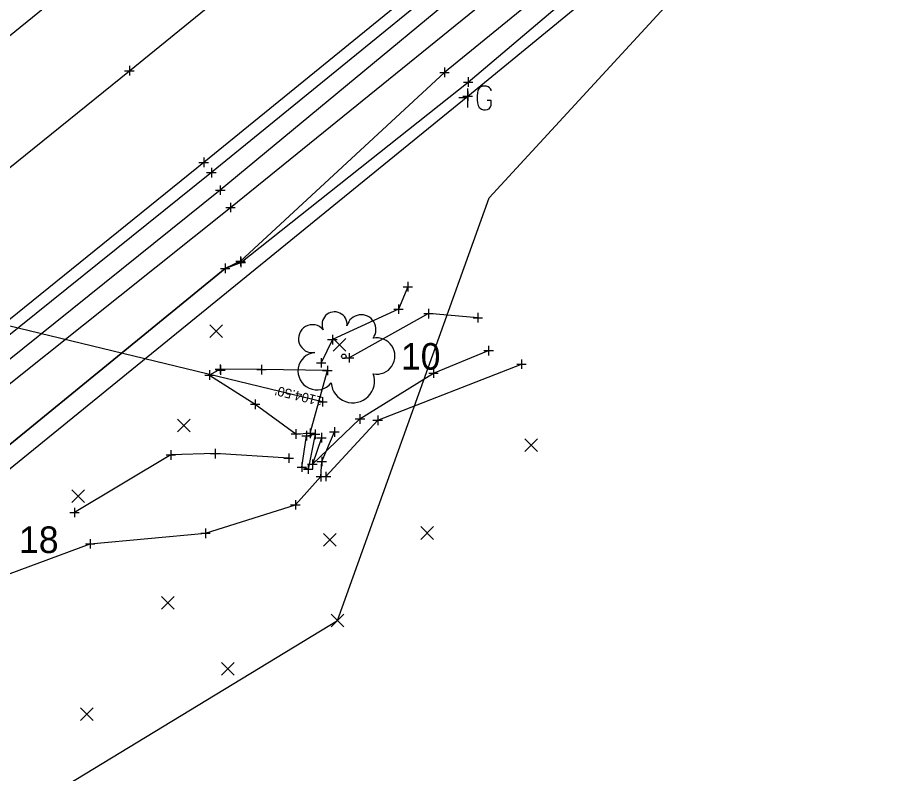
# Model space of a CAD drawing. Extents: x 2184635 to 2185378, y 369880 to 370486.
# Drawn here: x 2185165.6 to 2185257.8, y 370246.3 to 370325.9 of the extents above; entities that cross this region are included whole.
import ezdxf

# ---------------------------------------------------------------- set-up
doc = ezdxf.new("R2010")
doc.units = 0
for name, color, linetype in [('_CIVIL_CONSTRUCTION', 7, 'Continuous'), ('DR_X_Ditch', 7, 'Continuous'), ('DR_X_Headwall', 7, 'Continuous'), ('DR_X_Storm_Sewer', 7, 'Continuous'), ('GE_X_Alignment', 7, 'Continuous'), ('GE_X_Alignment_100_Bearings', 7, 'Continuous'), ('GE_X_Alignment_100_Distances', 7, 'Continuous'), ('PM_X_CL_Pass_Proh_Lt', 7, 'Continuous'), ('PM_X_CL_Pass_Proh_Rt', 7, 'Continuous'), ('PM_X_Edge_Line', 7, 'Continuous'), ('PV_X_COP', 7, 'Continuous'), ('PV_X_EOP', 7, 'Continuous'), ('PV_X_Shoulder', 7, 'Continuous'), ('RD_X_Fence', 7, 'Continuous'), ('RD_X_GR_Rt', 7, 'Continuous'), ('RW_X_CL', 7, 'Continuous'), ('RW_X_CL_100_Bearings', 7, 'Continuous'), ('SC_Scratch1', 7, 'Continuous'), ('SV_X_Break_Lines', 7, 'Continuous'), ('SV_X_Terrain_Boundary', 7, 'Continuous'), ('SV_X_Void_Area', 7, 'Continuous'), ('UT_X_Gas', 7, 'Continuous'), ('VG_X_Text', 7, 'Continuous')]:
    doc.layers.add(name, color=color, linetype=linetype)

msp = doc.modelspace()

# ---------------------------------------------------------------- linework, layer by layer
at = {"layer": '_CIVIL_CONSTRUCTION'}
for p, q in [((2185185.826, 370292.22), (2185187.159, 370293.555)), ((2185185.826, 370293.555), (2185187.159, 370292.22)), ((2185198.792, 370290.805), (2185200.125, 370292.14)), ((2185198.792, 370292.14), (2185200.125, 370290.805)), ((2185182.401, 370282.304), (2185183.735, 370283.639)), ((2185182.401, 370283.639), (2185183.735, 370282.304)), ((2185218.974, 370280.234), (2185220.307, 370281.569)), ((2185218.974, 370281.569), (2185220.307, 370280.234)), ((2185171.289, 370274.86), (2185172.622, 370276.195)), ((2185171.289, 370276.195), (2185172.622, 370274.86)), ((2185208.013, 370270.987), (2185209.347, 370272.322)), ((2185208.013, 370272.322), (2185209.347, 370270.987)), ((2185197.799, 370270.269), (2185199.132, 370271.603)), ((2185197.799, 370271.603), (2185199.132, 370270.269)), ((2185180.748, 370263.643), (2185182.082, 370264.978)), ((2185180.748, 370264.978), (2185182.082, 370263.643)), ((2185198.603, 370261.776), (2185199.937, 370263.111)), ((2185198.603, 370263.111), (2185199.937, 370261.776)), ((2185187.046, 370256.677), (2185188.379, 370258.012)), ((2185187.046, 370258.012), (2185188.379, 370256.677)), ((2185172.22, 370251.931), (2185173.554, 370253.266)), ((2185172.22, 370253.266), (2185173.554, 370251.931))]:
    msp.add_line(p, q, dxfattribs=at)
at = {"layer": 'DR_X_Ditch'}
msp.add_lwpolyline([(2185149.532, 370261.732), (2185173.227, 370270.512), (2185185.361, 370271.623), (2185194.823, 370274.626), (2185197.504, 370277.588), (2185197.594, 370279.178), (2185198.93, 370282.292)], dxfattribs=at)
at = {"layer": 'DR_X_Headwall'}
msp.add_lwpolyline([(2185196.907, 370282.047), (2185196.172, 370278.374), (2185195.503, 370278.59), (2185196.005, 370281.891)], close=True, dxfattribs=at)
at = {"layer": 'DR_X_Storm_Sewer'}
msp.add_line((2185197.669, 370285.467), (2185098.296, 370309.544), dxfattribs=at)
at = {"layer": 'GE_X_Alignment'}
msp.add_circle((2185199.926, 370290.245), 0.24, dxfattribs=at)
for centre, radius, start, end in [((2185198.942, 370293.613), 1.317, 354.0047, 205.97412), ((2185201.752, 370293.074), 1.553, 323.82996, 165.0376), ((2185196.616, 370292.109), 1.471, 39.06254, 279.54124), ((2185203.386, 370290.281), 1.915, 259.14531, 101.45961), ((2185197.072, 370288.697), 1.974, 96.17219, 320.57371), ((2185200.872, 370287.64), 2.284, 184.94757, 19.45715)]:
    msp.add_arc(centre, radius, start, end, dxfattribs=at)
at = {"layer": 'GE_X_Alignment_100_Bearings'}
for p, q in [((2185212.96, 370316.445), (2185212.96, 370318.445)), ((2185212.96, 370317.445), (2185212.008, 370317.445))]:
    msp.add_line(p, q, dxfattribs=at)
msp.add_lwpolyline([(2185215.437, 370318.201), (2185215.417, 370318.299), (2185215.358, 370318.398), (2185215.259, 370318.496), (2185215.122, 370318.614), (2185215.023, 370318.654), (2185214.944, 370318.673), (2185214.826, 370318.693), (2185214.59, 370318.693), (2185214.492, 370318.673), (2185214.433, 370318.654), (2185214.354, 370318.614), (2185214.196, 370318.496), (2185214.098, 370318.358), (2185214.039, 370318.201), (2185214, 370317.984), (2185213.96, 370317.669), (2185213.96, 370317.256), (2185213.98, 370316.921), (2185214.059, 370316.665), (2185214.177, 370316.429), (2185214.275, 370316.351), (2185214.393, 370316.272), (2185214.61, 370316.193), (2185214.826, 370316.193), (2185215.043, 370316.232), (2185215.122, 370316.272), (2185215.2, 370316.311), (2185215.279, 370316.39), (2185215.358, 370316.508), (2185215.437, 370316.685), (2185215.437, 370317.177), (2185215.023, 370317.177)], dxfattribs=at)
at = {"layer": 'GE_X_Alignment_100_Distances'}
msp.add_lwpolyline([(2185264.317, 370371.308), (2185225.669, 370339.838), (2185186.917, 370307.744), (2185148.745, 370277.089), (2185109.073, 370245.724), (2185070.468, 370214.753), (2185031.044, 370183.419), (2184991.951, 370153.137), (2184952.243, 370122.384), (2184912.885, 370091.687), (2184876.597, 370062.99), (2184874.528, 370062.204), (2184872.479, 370060.466), (2184871.454, 370058.823), (2184869.46, 370057.791), (2184834.83, 370028.947), (2184796.151, 369998.173), (2184773.728, 369979.618), (2184757.686, 369965.832), (2184717.275, 369935.855), (2184678.357, 369904.181)], dxfattribs=at)
at = {"layer": 'PM_X_CL_Pass_Proh_Lt'}
msp.add_lwpolyline([(2185262.142, 370374.202), (2185223.699, 370342.03), (2185185.178, 370310.659), (2185146.677, 370279.544), (2185107.738, 370248.35), (2185068.5, 370216.963), (2185029.051, 370186.04), (2184989.472, 370156.275), (2184949.89, 370125.369), (2184910.765, 370094.563), (2184870.979, 370063.529), (2184832.077, 370032.401), (2184793.204, 370001.486), (2184754.34, 369970.024), (2184715.121, 369938.505), (2184676.144, 369907.221)], dxfattribs=at)
at = {"layer": 'PM_X_CL_Pass_Proh_Rt'}
msp.add_lwpolyline([(2184772.075, 369998.33), (2184786.357, 370009.443), (2184824.962, 370040.257), (2184864.241, 370071.885), (2184905.968, 370104.805), (2184943.399, 370133.995), (2184983.483, 370165.213), (2185020.257, 370194.467), (2185061.224, 370226.635), (2185099.743, 370257.779), (2185139.182, 370289.511), (2185177.352, 370320.307), (2185216.054, 370351.804), (2185254.728, 370383.452)], dxfattribs=at)
at = {"layer": 'PM_X_Edge_Line'}
msp.add_lwpolyline([(2184661.525, 369922.948), (2184702.122, 369955.424), (2184740.459, 369986.306), (2184779.792, 370018.036), (2184818.421, 370048.832), (2184857.458, 370080.192), (2184899.139, 370112.801), (2184937.357, 370142.735), (2184976.78, 370173.64), (2185013.226, 370203.926), (2185054.743, 370235.213), (2185093.131, 370266.204), (2185132.902, 370298.208), (2185170.876, 370328.987), (2185209.713, 370360.437), (2185248.243, 370392.049)], dxfattribs=at)
at = {"layer": 'PV_X_COP'}
msp.add_lwpolyline([(2184667.936, 369914.544), (2184708.437, 369946.755), (2184746.444, 369977.522), (2184786.357, 370009.443), (2184824.962, 370040.257), (2184864.241, 370071.885), (2184905.968, 370104.805), (2184943.399, 370133.995), (2184983.483, 370165.213), (2185020.257, 370194.467), (2185061.224, 370226.635), (2185099.743, 370257.779), (2185139.182, 370289.511), (2185177.352, 370320.307), (2185216.054, 370351.804), (2185254.679, 370383.196)], dxfattribs=at)
at = {"layer": 'PV_X_EOP'}
for points in [[(2184661.562, 369922.858), (2184702.122, 369955.424), (2184740.459, 369986.306), (2184779.792, 370018.036), (2184818.421, 370048.832), (2184857.458, 370080.192), (2184899.139, 370112.801), (2184937.357, 370142.735), (2184976.78, 370173.64), (2185013.226, 370203.926), (2185054.743, 370235.213), (2185093.131, 370266.204), (2185132.902, 370298.208), (2185170.876, 370328.987), (2185209.713, 370360.437), (2185248.181, 370392.045)], [(2185262.152, 370374.256), (2185223.699, 370342.03), (2185185.178, 370310.659), (2185146.677, 370279.544), (2185107.738, 370248.35), (2185068.5, 370216.963), (2185029.051, 370186.04), (2184989.472, 370156.275), (2184949.89, 370125.369), (2184910.765, 370094.563), (2184870.979, 370063.529), (2184832.077, 370032.401), (2184793.204, 370001.486), (2184754.34, 369970.024), (2184715.121, 369938.505), (2184676.223, 369907.131)]]:
    msp.add_lwpolyline(points, dxfattribs=at)
at = {"layer": 'PV_X_Shoulder'}
msp.add_lwpolyline([(2185263.127, 370373.08), (2185224.626, 370341.08), (2185185.979, 370309.587), (2185147.251, 370278.484), (2185108.316, 370247.412), (2185069.303, 370216.141), (2185029.865, 370185.151), (2184990.36, 370154.899), (2184951.083, 370123.826), (2184911.784, 370093.315), (2184872.077, 370062.156), (2184833.336, 370030.958), (2184794.18, 369999.967), (2184755.603, 369968.652), (2184716.02, 369937.324), (2184677.487, 369905.633)], dxfattribs=at)
at = {"layer": 'RD_X_Fence'}
msp.add_lwpolyline([(2184974.137, 370097.077), (2184970.447, 370119.306), (2184979.406, 370128.641), (2184992.607, 370140.381), (2185007.827, 370153.847), (2185011.099, 370157.209), (2185036.107, 370177.129), (2185063.41, 370198.922), (2185078.716, 370210.935), (2185113.226, 370240.316), (2185152.641, 370271.084), (2185187.441, 370299.506), (2185189.075, 370300.14), (2185213.006, 370319.114), (2185230.361, 370333.854), (2185268.576, 370364.897)], dxfattribs=at)
at = {"layer": 'RD_X_GR_Rt'}
msp.add_lwpolyline([(2184986.918, 370145.362), (2184992.997, 370150.672), (2185032.04, 370181.661), (2185071.402, 370212.899), (2185110.342, 370243.768), (2185149.195, 370274.959), (2185188, 370305.912), (2185226.97, 370337.52), (2185265.615, 370369.567), (2185308.993, 370405.417), (2185377.709, 370462.246)], dxfattribs=at)
at = {"layer": 'RW_X_CL'}
for p, q in [((2185176.852, 370320.307), (2185177.852, 370320.307)), ((2185176.852, 370320.307), (2185177.852, 370320.307)), ((2185177.352, 370320.807), (2185177.352, 370319.807)), ((2185177.352, 370320.807), (2185177.352, 370319.807)), ((2185177.352, 370320.307), (2185177.352, 370320.307)), ((2185177.352, 370320.307), (2185177.352, 370320.307)), ((2185210.015, 370320.131), (2185211.015, 370320.131)), ((2185210.515, 370320.631), (2185210.515, 370319.631)), ((2185210.515, 370320.131), (2185210.515, 370320.131)), ((2185212.506, 370319.114), (2185213.506, 370319.114)), ((2185213.006, 370319.614), (2185213.006, 370318.614)), ((2185213.006, 370319.114), (2185213.006, 370319.114)), ((2185212.455, 370317.623), (2185213.455, 370317.623)), ((2185212.955, 370318.123), (2185212.955, 370317.123)), ((2185212.955, 370317.623), (2185212.955, 370317.623)), ((2185185.178, 370311.159), (2185185.178, 370310.159)), ((2185185.178, 370311.159), (2185185.178, 370310.159)), ((2185184.678, 370310.659), (2185185.678, 370310.659)), ((2185184.678, 370310.659), (2185185.678, 370310.659)), ((2185185.178, 370310.659), (2185185.178, 370310.659)), ((2185185.178, 370310.659), (2185185.178, 370310.659)), ((2185185.979, 370310.087), (2185185.979, 370309.087)), ((2185185.479, 370309.587), (2185186.479, 370309.587)), ((2185185.979, 370309.587), (2185185.979, 370309.587)), ((2185186.917, 370308.244), (2185186.917, 370307.244)), ((2185186.417, 370307.744), (2185187.417, 370307.744)), ((2185186.917, 370307.744), (2185186.917, 370307.744)), ((2185188, 370306.412), (2185188, 370305.412)), ((2185187.5, 370305.912), (2185188.5, 370305.912)), ((2185188, 370305.912), (2185188, 370305.912)), ((2185189.044, 370300.771), (2185189.044, 370299.771)), ((2185189.075, 370300.64), (2185189.075, 370299.64)), ((2185187.441, 370300.006), (2185187.441, 370299.006)), ((2185187.441, 370300.006), (2185187.441, 370299.006)), ((2185188.544, 370300.271), (2185189.544, 370300.271)), ((2185188.575, 370300.14), (2185189.575, 370300.14)), ((2185189.044, 370300.271), (2185189.044, 370300.271)), ((2185189.075, 370300.14), (2185189.075, 370300.14)), ((2185186.941, 370299.506), (2185187.941, 370299.506)), ((2185186.941, 370299.506), (2185187.941, 370299.506)), ((2185187.441, 370299.506), (2185187.441, 370299.506)), ((2185187.441, 370299.506), (2185187.441, 370299.506)), ((2185206.663, 370298.075), (2185206.663, 370297.075)), ((2185206.163, 370297.575), (2185207.163, 370297.575)), ((2185206.663, 370297.575), (2185206.663, 370297.575)), ((2185205.175, 370295.217), (2185206.175, 370295.217)), ((2185205.675, 370295.717), (2185205.675, 370294.717)), ((2185205.675, 370295.217), (2185205.675, 370295.217)), ((2185208.837, 370295.241), (2185208.837, 370294.241)), ((2185208.337, 370294.741), (2185209.337, 370294.741)), ((2185208.837, 370294.741), (2185208.837, 370294.741)), ((2185213.525, 370294.318), (2185214.525, 370294.318)), ((2185214.025, 370294.818), (2185214.025, 370293.818)), ((2185214.025, 370294.318), (2185214.025, 370294.318)), ((2185198.713, 370292.511), (2185198.713, 370291.511)), ((2185198.213, 370292.011), (2185199.213, 370292.011)), ((2185198.713, 370292.011), (2185198.713, 370292.011)), ((2185200.479, 370290.582), (2185200.479, 370289.582)), ((2185214.658, 370290.849), (2185215.658, 370290.849)), ((2185215.158, 370291.349), (2185215.158, 370290.349)), ((2185215.158, 370290.849), (2185215.158, 370290.849)), ((2185197.038, 370289.572), (2185198.038, 370289.572)), ((2185197.538, 370290.072), (2185197.538, 370289.072)), ((2185197.538, 370289.572), (2185197.538, 370289.572)), ((2185199.979, 370290.082), (2185200.979, 370290.082)), ((2185200.479, 370290.082), (2185200.479, 370290.082)), ((2185218.62, 370289.923), (2185218.62, 370288.923)), ((2185185.785, 370288.783), (2185185.785, 370287.783)), ((2185186.394, 370288.897), (2185187.394, 370288.897)), ((2185186.446, 370288.807), (2185187.446, 370288.807)), ((2185186.894, 370289.397), (2185186.894, 370288.397)), ((2185186.894, 370288.897), (2185186.894, 370288.897)), ((2185186.946, 370289.307), (2185186.946, 370288.307)), ((2185186.946, 370288.807), (2185186.946, 370288.807)), ((2185190.762, 370288.846), (2185191.762, 370288.846)), ((2185191.262, 370289.346), (2185191.262, 370288.346)), ((2185191.262, 370288.846), (2185191.262, 370288.846)), ((2185197.69, 370288.761), (2185198.69, 370288.761)), ((2185198.19, 370289.261), (2185198.19, 370288.261)), ((2185198.19, 370288.761), (2185198.19, 370288.761)), ((2185209.365, 370288.989), (2185209.365, 370287.989)), ((2185218.12, 370289.423), (2185219.12, 370289.423)), ((2185218.62, 370289.423), (2185218.62, 370289.423)), ((2185185.285, 370288.283), (2185186.285, 370288.283)), ((2185185.785, 370288.283), (2185185.785, 370288.283)), ((2185208.865, 370288.489), (2185209.865, 370288.489)), ((2185209.365, 370288.489), (2185209.365, 370288.489)), ((2185190.091, 370285.205), (2185191.091, 370285.205)), ((2185190.591, 370285.705), (2185190.591, 370284.705)), ((2185190.591, 370285.205), (2185190.591, 370285.205)), ((2185201.618, 370284.155), (2185201.618, 370283.155)), ((2185201.118, 370283.655), (2185202.118, 370283.655)), ((2185201.618, 370283.655), (2185201.618, 370283.655)), ((2185202.984, 370283.52), (2185203.984, 370283.52)), ((2185203.484, 370284.02), (2185203.484, 370283.02)), ((2185203.484, 370283.52), (2185203.484, 370283.52)), ((2185194.877, 370282.578), (2185194.877, 370281.578)), ((2185196.005, 370282.391), (2185196.005, 370281.391)), ((2185196.387, 370282.651), (2185196.387, 370281.651)), ((2185196.907, 370282.547), (2185196.907, 370281.547)), ((2185198.43, 370282.292), (2185199.43, 370282.292)), ((2185198.93, 370282.792), (2185198.93, 370281.792)), ((2185198.93, 370282.292), (2185198.93, 370282.292)), ((2185194.377, 370282.078), (2185195.377, 370282.078)), ((2185194.877, 370282.078), (2185194.877, 370282.078)), ((2185195.505, 370281.891), (2185196.505, 370281.891)), ((2185195.887, 370282.151), (2185196.887, 370282.151)), ((2185196.005, 370281.891), (2185196.005, 370281.891)), ((2185196.387, 370282.151), (2185196.387, 370282.151)), ((2185196.407, 370282.047), (2185197.407, 370282.047)), ((2185196.907, 370282.047), (2185196.907, 370282.047)), ((2185197.062, 370281.68), (2185198.062, 370281.68)), ((2185197.562, 370282.18), (2185197.562, 370281.18)), ((2185197.562, 370281.68), (2185197.562, 370281.68)), ((2185181.717, 370280.37), (2185181.717, 370279.37)), ((2185186.369, 370280.513), (2185186.369, 370279.513)), ((2185181.217, 370279.87), (2185182.217, 370279.87)), ((2185181.717, 370279.87), (2185181.717, 370279.87)), ((2185185.869, 370280.013), (2185186.869, 370280.013)), ((2185186.369, 370280.013), (2185186.369, 370280.013)), ((2185193.621, 370279.532), (2185194.621, 370279.532)), ((2185194.121, 370280.032), (2185194.121, 370279.032)), ((2185194.121, 370279.532), (2185194.121, 370279.532)), ((2185197.594, 370279.678), (2185197.594, 370278.678)), ((2185195.003, 370278.59), (2185196.003, 370278.59)), ((2185195.503, 370279.09), (2185195.503, 370278.09)), ((2185195.503, 370278.59), (2185195.503, 370278.59)), ((2185196.114, 370278.887), (2185197.114, 370278.887)), ((2185196.172, 370278.874), (2185196.172, 370277.874)), ((2185196.614, 370279.387), (2185196.614, 370278.387)), ((2185196.614, 370278.887), (2185196.614, 370278.887)), ((2185197.094, 370279.178), (2185198.094, 370279.178)), ((2185197.594, 370279.178), (2185197.594, 370279.178)), ((2185195.672, 370278.374), (2185196.672, 370278.374)), ((2185196.172, 370278.374), (2185196.172, 370278.374)), ((2185197.004, 370277.588), (2185198.004, 370277.588)), ((2185197.504, 370278.088), (2185197.504, 370277.088)), ((2185197.504, 370277.588), (2185197.504, 370277.588)), ((2185197.539, 370277.601), (2185198.539, 370277.601)), ((2185198.039, 370278.101), (2185198.039, 370277.101)), ((2185198.039, 370277.601), (2185198.039, 370277.601)), ((2185194.823, 370275.126), (2185194.823, 370274.126)), ((2185171.575, 370274.318), (2185171.575, 370273.318)), ((2185194.323, 370274.626), (2185195.323, 370274.626)), ((2185194.823, 370274.626), (2185194.823, 370274.626)), ((2185171.075, 370273.818), (2185172.075, 370273.818)), ((2185171.575, 370273.818), (2185171.575, 370273.818)), ((2185185.361, 370272.123), (2185185.361, 370271.123)), ((2185184.861, 370271.623), (2185185.861, 370271.623)), ((2185185.361, 370271.623), (2185185.361, 370271.623)), ((2185172.727, 370270.512), (2185173.727, 370270.512)), ((2185173.227, 370271.012), (2185173.227, 370270.012)), ((2185173.227, 370270.512), (2185173.227, 370270.512))]:
    msp.add_line(p, q, dxfattribs=at)
at = {"layer": 'RW_X_CL_100_Bearings'}
for p, q in [((2185197.669, 370285.967), (2185197.669, 370284.967)), ((2185197.169, 370285.467), (2185198.169, 370285.467)), ((2185197.669, 370285.467), (2185197.669, 370285.467))]:
    msp.add_line(p, q, dxfattribs=at)
at = {"layer": 'SV_X_Break_Lines'}
for points in [[(2185266.896, 370366.662), (2185229.269, 370335.467), (2185210.515, 370320.131), (2185189.044, 370300.271), (2185187.441, 370299.506), (2185152.641, 370271.084), (2185113.226, 370240.316), (2185078.716, 370210.935), (2185063.41, 370198.922), (2185036.107, 370177.129), (2185008.734, 370156.161), (2184994.285, 370149.68)], [(2185206.663, 370297.575), (2185205.675, 370295.217), (2185198.713, 370292.011), (2185197.538, 370289.572)], [(2185214.025, 370294.318), (2185208.837, 370294.741), (2185200.479, 370290.082)], [(2185197.562, 370281.68), (2185196.614, 370278.887), (2185201.618, 370283.655), (2185209.365, 370288.489), (2185215.158, 370290.849)], [(2185198.039, 370277.601), (2185203.484, 370283.52), (2185218.62, 370289.423)], [(2185194.121, 370279.532), (2185186.369, 370280.013), (2185181.717, 370279.87), (2185171.575, 370273.818)]]:
    msp.add_lwpolyline(points, dxfattribs=at)
at = {"layer": 'SV_X_Terrain_Boundary'}
msp.add_lwpolyline([(2184974.137, 370097.077), (2185033.603, 370139.079), (2185056.498, 370157.156), (2185084.693, 370178.208), (2185162.576, 370240.184), (2185199.27, 370262.443), (2185215.204, 370306.943), (2185268.576, 370364.897), (2185258.835, 370377.241), (2185248.181, 370392.045), (2185238.668, 370405.318), (2185197.578, 370376.275), (2185164.413, 370344.459), (2185149.44, 370353.437), (2185069.982, 370323.057), (2185048.788, 370280.746), (2184981.838, 370244.628)], dxfattribs=at)
at = {"layer": 'SV_X_Void_Area'}
msp.add_lwpolyline([(2185198.19, 370288.761), (2185191.262, 370288.846), (2185186.894, 370288.897), (2185185.785, 370288.283), (2185190.591, 370285.205), (2185194.877, 370282.078), (2185196.387, 370282.151)], close=True, dxfattribs=at)
at = {"layer": 'UT_X_Gas'}
msp.add_lwpolyline([(2184953.242, 370098.442), (2184967.159, 370111.339), (2184998.214, 370137.606), (2185039.424, 370172.123), (2185069.412, 370195.978), (2185086.695, 370210.093), (2185109.697, 370228.178), (2185131.189, 370247.901), (2185147.466, 370264.362), (2185212.955, 370317.623), (2185242.558, 370341.915), (2185269.196, 370362.683)], dxfattribs=at)

# ---------------------------------------------------------------- texts
at = {"layer": 'SC_Scratch1'}
msp.add_text("1104.50'", height=1, rotation=166.38022, dxfattribs=at).set_placement((2185197.787, 370285.953))
at = {"layer": 'VG_X_Text'}
for s, p in [('10', (2185205.926, 370288.845)), ('18 ', (2185165.739, 370269.545))]:
    msp.add_text(s, height=2.8, dxfattribs=at).set_placement(p)

doc.saveas('drawing.dxf')
